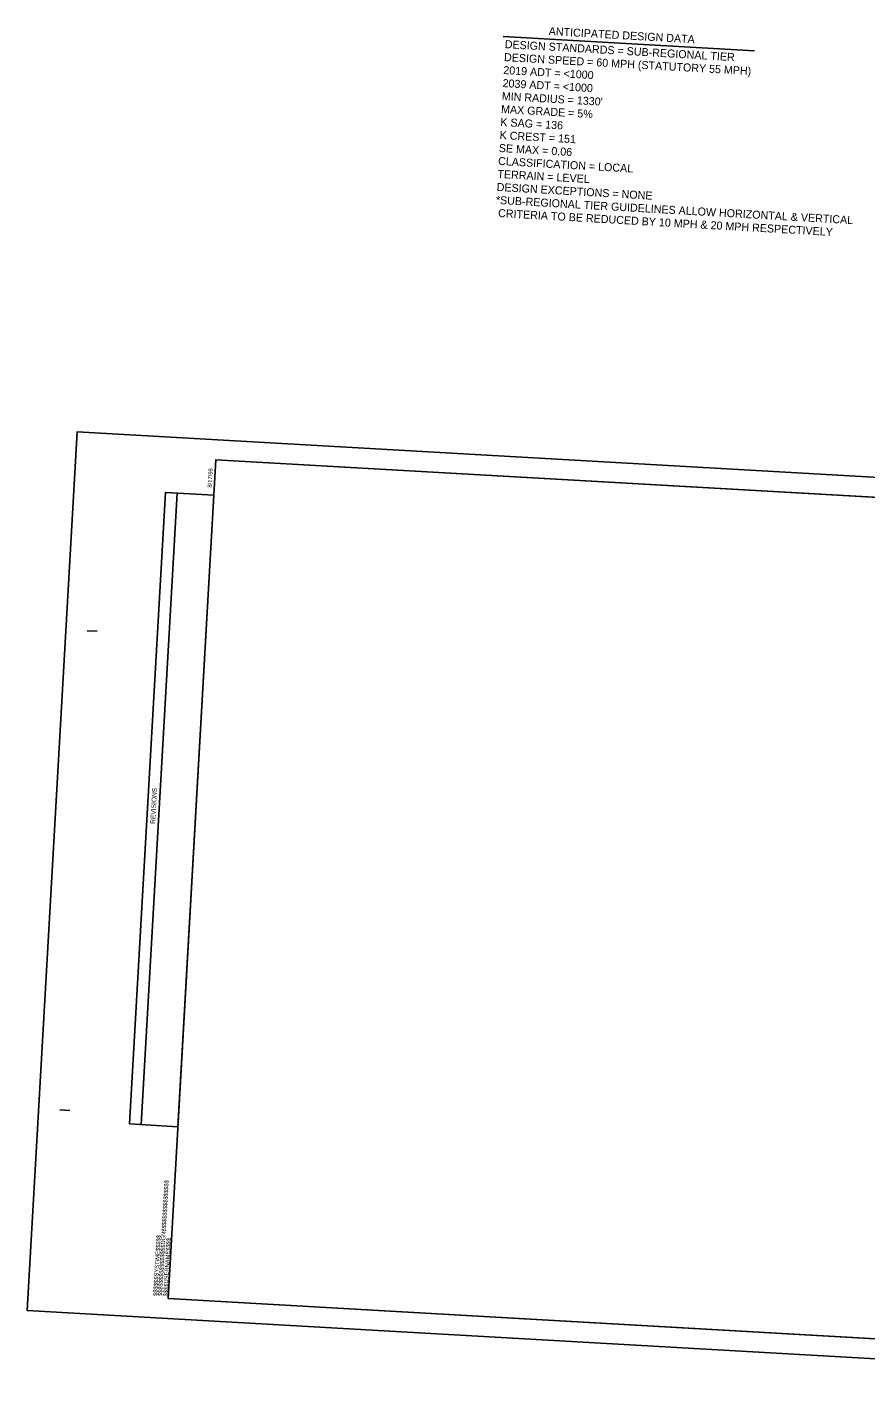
# Model space of a CAD drawing. Extents: x 2602909 to 2604669, y 617940 to 619640.
# Drawn here: x 2602909 to 2603958, y 617940 to 619640 of the extents above; entities that cross this region are included whole.
import ezdxf

# ---------------------------------------------------------------- set-up
doc = ezdxf.new("R2010")
doc.units = 0
for name, color, linetype in [('Scratch_Level_1', 7, 'Continuous'), ('Sheet Block Revision CELL', 7, 'Continuous'), ('Sheet Block System Information CELL', 7, 'Continuous'), ('Sheet Data Text CELL', 7, 'Continuous'), ('Sheet Plan And Profile CELL', 7, 'Continuous'), ('Stewart Plot Border Xerox6279 and LJ5000', 7, 'Continuous')]:
    doc.layers.add(name, color=color, linetype=linetype)

msp = doc.modelspace()

# ---------------------------------------------------------------- linework, layer by layer
at = {"layer": 'Scratch_Level_1'}
msp.add_lwpolyline([(2604574.9, 618817.1), (2604431.3, 618825.2), (2604442.8, 619026), (2603144.9, 619099.9), (2603085.2, 618051.6), (2604526.6, 617969.5)], close=True, dxfattribs=at)
msp.add_lwpolyline([(2604574.9, 618817.1), (2604431.3, 618825.2), (2604442.8, 619026), (2603144.9, 619099.9), (2603085.2, 618051.6), (2604526.6, 617969.5)], close=True, dxfattribs=at)
at = {"layer": 'Sheet Block Revision CELL'}
msp.add_line((2603051.5, 618268.9), (2603096.5, 619058.2), dxfattribs=at)
msp.add_lwpolyline([(2603037, 618269.7), (2603081.9, 619059), (2603142.4, 619055.6), (2603097.4, 618266.2)], close=True, dxfattribs=at)
at = {"layer": 'Sheet Block System Information CELL'}
msp.add_line((2603085.2, 618051.6), (2603085.2, 618051.6), dxfattribs=at)
at = {"layer": 'Sheet Data Text CELL'}
msp.add_line((2603504, 619628.9), (2603818.5, 619611), dxfattribs=at)
at = {"layer": 'Sheet Plan And Profile CELL'}
for p, q in [((2602984, 618886.2), (2602996.5, 618885.5)), ((2602949.9, 618287.2), (2602962.4, 618286.4)), ((2603085.2, 618051.6), (2603085.2, 618051.6)), ((2603085.2, 618051.6), (2603085.2, 618051.6)), ((2603085.2, 618051.6), (2603085.2, 618051.6)), ((2603085.2, 618051.6), (2603085.2, 618051.6)), ((2603085.2, 618051.6), (2603085.2, 618051.6))]:
    msp.add_line(p, q, dxfattribs=at)
msp.add_lwpolyline([(2604642.5, 619014.6), (2603144.9, 619099.9), (2603085.2, 618051.6), (2604582.8, 617966.3)], close=True, dxfattribs=at)
at = {"layer": 'Stewart Plot Border Xerox6279 and LJ5000'}
msp.add_lwpolyline([(2602909.1, 618036.6), (2604606.3, 617939.9), (2604668.9, 619038.1), (2602971.6, 619134.8)], close=True, dxfattribs=at)

# ---------------------------------------------------------------- texts
at = {"layer": 'Sheet Block Revision CELL'}
msp.add_text('REVISIONS', height=6, rotation=86.7403, dxfattribs=at).set_placement((2603068.9, 618644.6))
at = {"layer": 'Sheet Block System Information CELL'}
for s, p in [('$$$$$$$$$$$$$$$$DGN$$$$$$$$$$$$$$$$', (2603077.7, 618054.4)), ('$$$$$$SYSTIME$$$$$', (2603071.7, 618054.7)), ('$$$$USERNAME$$$$', (2603084.3, 618054))]:
    msp.add_text(s, height=5.25, rotation=86.7403, dxfattribs=at).set_placement(p)
at = {"layer": 'Sheet Data Text CELL'}
for s, p in [('ANTICIPATED DESIGN DATA', (2603560.9, 619630.7)), ('DESIGN STANDARDS = SUB-REGIONAL TIER', (2603505.9, 619614.4)), ('DESIGN SPEED = 60 MPH (STATUTORY 55 MPH)', (2603505, 619598.2)), ('2019 ADT = <1000', (2603504.1, 619582)), ('2039 ADT = <1000', (2603503.2, 619565.7)), ('MAX GRADE = 5%', (2603501.3, 619533.3)), ("MIN RADIUS = 1330'", (2603502.2, 619549.5)), ('K SAG = 136', (2603500.4, 619517.1)), ('K CREST = 151', (2603499.5, 619500.8)), ('SE MAX = 0.06', (2603498.5, 619484.6)), ('CLASSIFICATION = LOCAL', (2603497.6, 619468.4)), ('TERRAIN = LEVEL', (2603496.7, 619452.2)), ('DESIGN EXCEPTIONS = NONE', (2603495.8, 619435.9)), ('*SUB-REGIONAL TIER GUIDELINES ALLOW HORIZONTAL & VERTICAL', (2603494.8, 619419.7)), (' CRITERIA TO BE REDUCED BY 10 MPH & 20 MPH RESPECTIVELY', (2603493.9, 619403.5))]:
    msp.add_text(s, height=10, rotation=356.7403, dxfattribs=at).set_placement(p)
at = {"layer": 'Sheet Plan And Profile CELL'}
msp.add_text('8/17/99', height=5.25, rotation=86.7403, dxfattribs=at).set_placement((2603139.7, 619064.9))

doc.saveas('drawing.dxf')
